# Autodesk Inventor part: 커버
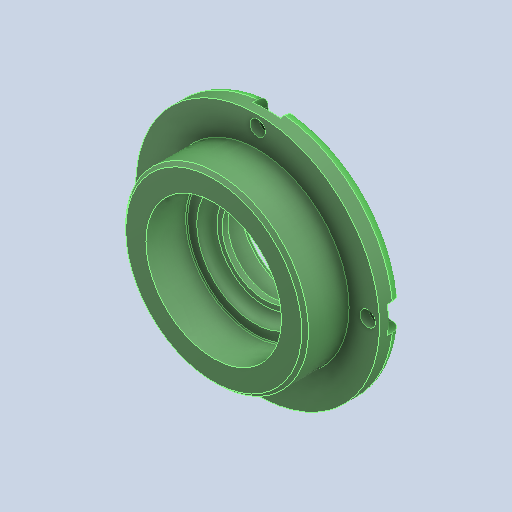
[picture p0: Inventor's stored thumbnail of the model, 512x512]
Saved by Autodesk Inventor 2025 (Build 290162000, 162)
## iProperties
Created: 2024-07
Part Number: 커버
Material: 강철, 연강
Document SubType Name: Modeling
Designer: SAMSUNG
Density: 7.86 g/cm^3
Appearance: 기본값
Company: 한국ATC센터
Author: jhkim
Revision Number: 1
Sending System: Autodesk Inventor 2025
Preprocessor: ST-DEVELOPER v20
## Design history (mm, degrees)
feature "솔리드1"
node "솔리드2"
